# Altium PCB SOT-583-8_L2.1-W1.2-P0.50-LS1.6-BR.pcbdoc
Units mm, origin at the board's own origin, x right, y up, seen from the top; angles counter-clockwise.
Board outline 14.66 x 15.12 mm, 2 copper layers (Top Layer, Bottom Layer), stack 0 mm thick; 1 components, 0 nets, 8 pads, 0 vias.
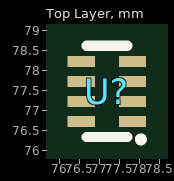
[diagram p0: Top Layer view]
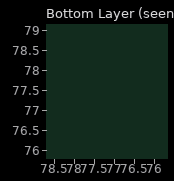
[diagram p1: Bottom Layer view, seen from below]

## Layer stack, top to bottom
Top Layer: signal copper (thickness not stored)
Bottom Layer: signal copper (thickness not stored)

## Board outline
84.51,69.85 69.85,69.85 69.85,84.968 84.51,84.968

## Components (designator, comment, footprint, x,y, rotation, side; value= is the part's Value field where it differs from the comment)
U? "" SOT-583-8_L2.1-W1.2-P0.50-LS1.6-BR 77.18,77.475 r0 top

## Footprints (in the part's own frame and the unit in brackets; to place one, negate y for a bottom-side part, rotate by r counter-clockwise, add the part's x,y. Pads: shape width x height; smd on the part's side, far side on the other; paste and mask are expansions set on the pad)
SOT-583-8_L2.1-W1.2-P0.50-LS1.6-BR [mm]
  rect 0.68x0.28 smd: 1(0.64,-0.75) 2(0.64,-0.25) 3(0.64,0.25) 4(0.64,0.75) 5(-0.64,0.75) 6(-0.64,0.25) 7(-0.64,-0.25) 8(-0.64,-0.75)
  silkscreen extent -0.51,-1.27 0.93,1.14

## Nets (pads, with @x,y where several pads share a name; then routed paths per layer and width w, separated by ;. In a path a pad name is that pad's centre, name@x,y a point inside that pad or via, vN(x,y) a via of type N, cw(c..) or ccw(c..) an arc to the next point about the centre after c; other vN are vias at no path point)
pads on no net: U?.1 U?.2 U?.3 U?.4 U?.5 U?.6 U?.7 U?.8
